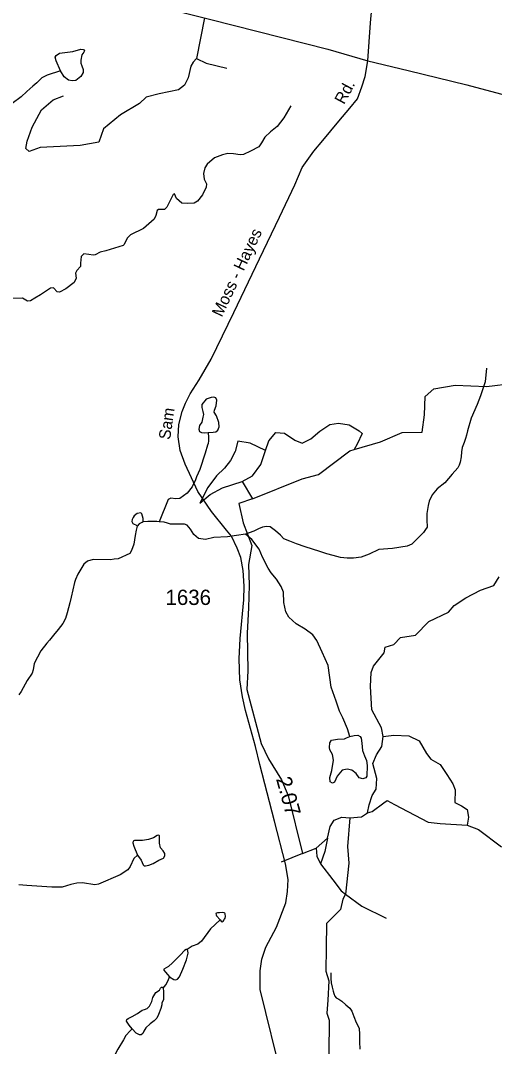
# Model space of a CAD drawing. Extents: x 2056842 to 2160602, y 826753 to 1016856.
# Drawn here: x 2101264 to 2105136, y 872458 to 880850 of the extents above; entities that cross this region are included whole.
import ezdxf

# ---------------------------------------------------------------- set-up
doc = ezdxf.new("R2010")
doc.units = 0
for name, color, linetype in [('Exist Hydrographic Misc Water Feature', 7, 'Continuous'), ('Exist Road Non-System Type 51', 7, 'Continuous'), ('Exist Road Secondary Mileage Hundredths English Label', 7, 'Continuous'), ('Exist Road Secondary Type 51 Attributed', 7, 'Continuous'), ('Exist Road Secondary Type 51 Label', 7, 'Continuous'), ('Exist Road Secondary Type 51 Number Label', 7, 'Continuous')]:
    doc.layers.add(name, color=color, linetype=linetype)

msp = doc.modelspace()

# ---------------------------------------------------------------- linework, layer by layer
at = {"layer": 'Exist Hydrographic Misc Water Feature'}
for points in [[(2101589.2, 880437.9), (2101555.1, 880520.6), (2101547.8, 880548.6), (2101555.1, 880564.4), (2101580.7, 880581.4), (2101690.1, 880597.3), (2101756.9, 880614.3), (2101778.8, 880611.8), (2101784.9, 880600.9), (2101780, 880591.2), (2101765.4, 880569.3), (2101756.9, 880524.3), (2101755.7, 880501.2), (2101765.4, 880478.1), (2101775.1, 880447.7), (2101775.1, 880423.3), (2101756.9, 880391.7), (2101714.4, 880360.1), (2101686.4, 880355.2), (2101654.8, 880361.3), (2101619.6, 880389.3), (2101589.2, 880437.9)], [(2101589.2, 880437.9), (2101482.2, 880401.5), (2101437.2, 880380.8), (2101397.5, 880340.9), (2101363.9, 880312.7), (2101315.7, 880268.5), (2101267.9, 880224.6), (2101196, 880172.2)], [(2103471.9, 880150.8), (2103413.6, 880054.7), (2103360.1, 879984.2), (2103306.6, 879939.2), (2103260.4, 879896.6), (2103233.7, 879850.4), (2103211.8, 879816.4), (2103143.7, 879779.9), (2103086.6, 879753.1), (2103058.6, 879751.9), (2103002.7, 879760.4), (2102956.8, 879761.9), (2102914.3, 879752.2), (2102848.6, 879725.4), (2102789.1, 879674.3), (2102769.6, 879645.1), (2102758.7, 879598.9), (2102763.5, 879552.7), (2102781.8, 879513.8), (2102780.6, 879485.8), (2102750.2, 879423.8), (2102710.1, 879370.9), (2102682.1, 879356.3), (2102628.6, 879352.7), (2102582.4, 879356.3), (2102538, 879392.8), (2102522.2, 879432.9), (2102511.2, 879426.8), (2102460.2, 879322.3), (2102439.5, 879305.2), (2102392.1, 879304), (2102379.9, 879295.5), (2102368.3, 879254), (2102356.1, 879224.8), (2102268.6, 879149.4), (2102162.9, 879097.1), (2102134.9, 879069.2), (2102109.4, 879018.1), (2102100.9, 879008.4), (2101959.9, 878964.6), (2101915.4, 878955.1), (2101872.9, 878932), (2101858.3, 878929.6), (2101820.6, 878936.9), (2101781.7, 878941.7), (2101758.6, 878919.8), (2101753.8, 878863.9), (2101753.8, 878838.4), (2101724.6, 878805.5), (2101713.6, 878782.4), (2101717.3, 878743.5), (2101701.5, 878705.8), (2101634.6, 878654.7), (2101582.4, 878629.2), (2101562.9, 878630.4), (2101533.8, 878663.2), (2101509.4, 878660.8), (2101428, 878604.9), (2101381.6, 878578.7), (2101345.1, 878556.8), (2101320.8, 878554.4), (2101279.5, 878579.9), (2101200.5, 878575.1)], [(2105070, 878007.1), (2105059, 877894.3), (2105022.6, 877780), (2104994.6, 877708.2), (2104946, 877597.5), (2104916, 877494.3), (2104908, 877458.3), (2104899.8, 877430.3), (2104888.1, 877398.4), (2104872.1, 877358.2), (2104866.6, 877322.1), (2104862.5, 877282.1), (2104854.7, 877238.3), (2104848.8, 877212), (2104836.9, 877191.9), (2104791.1, 877140), (2104731.3, 877067.9), (2104667.5, 877019.6), (2104627.7, 876969.6), (2104602.1, 876917.4), (2104593.9, 876883.4), (2104582, 876817.5), (2104582.6, 876785.3), (2104584.5, 876765.6), (2104585.3, 876706.8), (2104573.1, 876686.2), (2104554.9, 876660.9), (2104499, 876603.7), (2104461.3, 876566), (2104422.4, 876550.2), (2104303.3, 876532), (2104191.5, 876522.2), (2104113.2, 876485.9), (2104045.6, 876461.7), (2103985.3, 876451.4), (2103933.2, 876453.6), (2103877.4, 876457.2), (2103817.6, 876475.1), (2103765.5, 876486.7), (2103709.3, 876506.6), (2103589.3, 876544.2), (2103519, 876568.3), (2103463, 876591.8), (2103414.8, 876611.7), (2103386.7, 876639.8), (2103347, 876675.5), (2103304.5, 876707.5), (2103272.5, 876711.2), (2103240.3, 876707.1), (2103206.9, 876693.1), (2103171, 876672.9), (2103102.7, 876648.8)], [(2102797.3, 877480.3), (2102836.2, 877482.7), (2102859.3, 877486.4), (2102876.3, 877498.5), (2102886.1, 877527.7), (2102884.9, 877560.6), (2102864.2, 877615.3), (2102846, 877645.7), (2102848.4, 877661.5), (2102863, 877698), (2102866.6, 877744.2), (2102858.1, 877762.4), (2102843.5, 877768.5), (2102821.7, 877766.1), (2102780.3, 877751.5), (2102746.3, 877710.2), (2102743.9, 877685.8), (2102752.4, 877650.6), (2102758.4, 877626.2), (2102753.6, 877605.6), (2102743.9, 877565.4), (2102726.8, 877536.2), (2102720.8, 877508.3), (2102726.8, 877487.6), (2102741.4, 877480.3), (2102768.2, 877477.9), (2102797.3, 877480.3)], [(2102797.3, 877480.3), (2102799.8, 877439), (2102800.5, 877411.6), (2102796.1, 877391.5), (2102790.9, 877375.7), (2102771.8, 877310.3), (2102728.1, 877177.7), (2102702.5, 877116.9), (2102694, 877092.6), (2102667.3, 877035.4), (2102624.8, 876984.2), (2102565.9, 876939.1), (2102531.9, 876938), (2102491.8, 876944.1), (2102471.1, 876933.2), (2102396.5, 876750.5)], [(2102264.7, 876748.2), (2102264.7, 876760), (2102264.7, 876776.2), (2102254.9, 876815.8), (2102246.5, 876822), (2102216.5, 876818), (2102192.7, 876798.1), (2102184.5, 876783.9), (2102176.7, 876767.6), (2102172.8, 876752), (2102180.6, 876735.8), (2102192.9, 876729.9), (2102205, 876726), (2102216.9, 876714)], [(2102216.9, 876714), (2102207.1, 876681.8), (2102199.3, 876638.1), (2102189.4, 876566.1), (2102169.6, 876515.9), (2102157.5, 876491.7), (2102061.7, 876447.5), (2102029.5, 876443.4), (2101997.5, 876439.4), (2101856.1, 876441.5), (2101811.1, 876426.9), (2101782, 876402.6), (2101732.1, 876321.1), (2101712.3, 876278.4), (2101704.5, 876254.5), (2101678.5, 876134.2), (2101665.1, 876086.4), (2101644.8, 876006.2), (2101631.3, 875958.4), (2101610.3, 875918.2), (2101571.6, 875870), (2101531.8, 875822), (2101500.1, 875781.9), (2101477.7, 875757.7), (2101430.1, 875693.9), (2101374.4, 875591.6), (2101367.3, 875538.1), (2101358.7, 875511.4), (2101317.4, 875453), (2101269.2, 875363.1), (2101249.3, 875334.9)], [(2102264.7, 876748.2), (2102256.9, 876744.1), (2102248.9, 876740.1), (2102233.1, 876733.9), (2102216.9, 876714)], [(2102396.5, 876750.5), (2102376.9, 876752.3), (2102304.5, 876752.3), (2102264.7, 876748.2)], [(2103102.7, 876648.8), (2102954.9, 876626.6), (2102843.4, 876622), (2102775.3, 876606), (2102717, 876613.5), (2102678.9, 876645.2), (2102651, 876689.2), (2102624.8, 876721.2), (2102604.5, 876729.2), (2102572.5, 876731.1), (2102524.9, 876731), (2102488.8, 876730.8), (2102464.6, 876738.6), (2102436.5, 876746.5), (2102396.5, 876750.5)], [(2103953.7, 874992.7), (2103934.3, 875055.9), (2103897.3, 875145.5), (2103869.2, 875201.4), (2103841.3, 875283.5), (2103800.6, 875396.7), (2103778, 875575.1), (2103727.5, 875682.9), (2103683.7, 875778.9), (2103651.3, 875826.4), (2103590.5, 875871.6), (2103515.2, 875914.2), (2103455.6, 875968.9), (2103431.3, 876012.4), (2103415.5, 876090.3), (2103412.4, 876173.8), (2103391.9, 876221.5), (2103356.2, 876279.7), (2103312.1, 876331.4), (2103286.1, 876371.5), (2103241.2, 876459.5), (2103213.3, 876526.9), (2103154.8, 876604.8), (2103102.7, 876648.8)], [(2103953.7, 874992.7), (2103989, 875002.4), (2104019.3, 875003.6), (2104038.8, 874993.9), (2104047.3, 874979.3), (2104050.9, 874938), (2104057, 874879.6), (2104072.8, 874835.8), (2104089.8, 874798.1), (2104094.7, 874756.8), (2104092.3, 874669.2), (2104086.2, 874655.8), (2104060.7, 874648.5), (2104031.5, 874655.8), (2104007.2, 874689.9), (2103970.7, 874717.8), (2103931.8, 874726.4), (2103890.5, 874717.8), (2103851.6, 874668), (2103829.7, 874620.6), (2103811.5, 874612), (2103793.3, 874623), (2103790.8, 874659.5), (2103807.9, 874716.6), (2103821.2, 874800.5), (2103813.9, 874845.5), (2103792.1, 874885.7), (2103788.4, 874902.7), (2103789.6, 874942.8), (2103805.4, 874963.5), (2103852.8, 874973.2), (2103910, 874974.4), (2103927, 874981.7), (2103953.7, 874992.7)], [(2102220, 874024), (2102248, 873982.3), (2102265, 873943.4), (2102274.7, 873934.9), (2102284.4, 873934.9), (2102311.2, 873942.2), (2102347.6, 873954.4), (2102393.8, 873983.5), (2102432.7, 873999.3), (2102442.4, 874016.4), (2102442.4, 874035.8), (2102427.9, 874058.9), (2102408.4, 874083.3), (2102399.9, 874122.2), (2102398.7, 874180.6), (2102393.8, 874186.6), (2102380.4, 874184.2), (2102348.8, 874166), (2102310, 874150.2), (2102260.1, 874142.9), (2102195.7, 874142.9), (2102183.5, 874136.8), (2102181.1, 874124.6), (2102188.4, 874096.6), (2102220, 874024)], [(2102220, 874024), (2102189.6, 873994.8), (2102160.5, 873931.6), (2102139.8, 873903.6), (2102078, 873862.3), (2101901.8, 873785.7), (2101871.4, 873779.6), (2101770.5, 873797.8), (2101724.4, 873795.4), (2101674.5, 873782), (2101604, 873761.4), (2101518.9, 873762.6), (2101314.3, 873775.4), (2101250.3, 873779.5)], [(2102894.8, 873494.5), (2102902.6, 873482.4), (2102911, 873478.7), (2102918.8, 873482.4), (2102926.8, 873494.6), (2102930.9, 873498.8), (2102934.8, 873506.8), (2102938.7, 873522.8), (2102936.5, 873542.6), (2102932.4, 873548.5), (2102928.5, 873550.7), (2102912.7, 873554.8), (2102888.9, 873552.6), (2102872.9, 873550.7), (2102864.7, 873548.2), (2102860.6, 873546.4), (2102860.8, 873534.2), (2102864.5, 873526.4), (2102894.8, 873494.5)], [(2102894.8, 873494.5), (2102817.1, 873420.3), (2102741.9, 873319.3), (2102711.5, 873295), (2102666.6, 873277.9), (2102625.2, 873251.2)], [(2102625.2, 873251.2), (2102618, 873252.4), (2102604.6, 873243.9), (2102569.3, 873208.6), (2102538.9, 873175.8), (2102506.1, 873141.7), (2102473.3, 873113.8), (2102435.6, 873090.7), (2102435.6, 873083.4), (2102449, 873066.3), (2102481.8, 873026.8)], [(2102481.8, 873026.8), (2102515.9, 873005.5), (2102532.9, 873004.3), (2102545, 873008), (2102563.3, 873028.6), (2102590, 873091.9), (2102619.2, 873167.3), (2102632.5, 873222), (2102631.3, 873241.5), (2102625.2, 873251.2)], [(2102428.3, 872934.4), (2102450.2, 872963.6), (2102470.9, 872997.6), (2102481.8, 873026.8)], [(2103798.1, 873059.5), (2103798.1, 873015.2), (2103802.4, 872977.7), (2103810.2, 872943.6), (2103818.6, 872911.5), (2103822.9, 872891.3), (2103830.7, 872869.5), (2103842.8, 872857.5), (2103864.5, 872845.7), (2103888.3, 872827.9), (2103921.1, 872799.8), (2103952.9, 872771.8), (2103971.1, 872748), (2103987.1, 872704.1), (2104005.4, 872655.9), (2104029.4, 872608.1), (2104033.9, 872556.3), (2104034.1, 872496.2), (2104035.9, 872436.2)], [(2102174.8, 872602.1), (2102150, 872631.6), (2102129.3, 872665.6), (2102131.8, 872677.8), (2102142.7, 872686.3), (2102175.5, 872704.5), (2102218.1, 872728.9), (2102257, 872755.6), (2102277.6, 872760.5), (2102299.5, 872770.2), (2102316.5, 872787.2), (2102336, 872827.4), (2102343.3, 872860.2), (2102370, 872900.3), (2102399.2, 872919.8), (2102407.7, 872935.6), (2102415, 872942.9), (2102421.1, 872942.9), (2102428.3, 872934.4)], [(2102428.3, 872934.4), (2102430.8, 872908.8), (2102432, 872865.1), (2102432, 872839.5), (2102418.6, 872816.4), (2102417.4, 872798.2), (2102408.9, 872770.2), (2102390.7, 872720.3), (2102376.1, 872691.2), (2102354.2, 872669.3), (2102323.8, 872644.9), (2102287.4, 872612.1), (2102271.6, 872584.1), (2102263, 872564.7), (2102249.7, 872553.7), (2102236.3, 872554.9), (2102207.1, 872568.3), (2102174.8, 872602.1)], [(2102174.8, 872602.1), (2102159, 872586.3), (2102125, 872547.4), (2102104.3, 872513.4), (2102059.3, 872435.5), (2102020.4, 872362.6), (2101962.1, 872294.7), (2101918.3, 872243.6), (2101900.1, 872225.4), (2101853.4, 872181.2)]]:
    msp.add_lwpolyline(points, dxfattribs=at)
at = {"layer": 'Exist Road Non-System Type 51'}
for p, q in [((2102766.6, 880870.3), (2102701.6, 880538.3)), ((2103074.5, 877079), (2103160, 876938.2)), ((2103678.8, 874080.3), (2103771.9, 874162)), ((2103568.6, 874036.5), (2103393.8, 873966.2)), ((2103568.6, 874036.5), (2103678.8, 874080.3))]:
    msp.add_line(p, q, dxfattribs=at)
for points in [[(2102701.6, 880538.3), (2102675, 880509.8), (2102654.1, 880475.5), (2102633.2, 880380.5), (2102602.8, 880319.6), (2102555.3, 880283.5), (2102395.7, 880249.3), (2102290.2, 880221.7), (2102237, 880172.3), (2102081.2, 880077.2), (2101942.5, 879963.1), (2101902.6, 879854.7), (2101749.6, 879827.1), (2101424.7, 879810), (2101335.3, 879779.6), (2101306.8, 879802.4), (2101318.2, 879863.3), (2101358.1, 879977.3), (2101434.2, 880120), (2101529.2, 880201.7), (2101614.7, 880234)], [(2102701.6, 880538.3), (2102779.5, 880502.2), (2102950.5, 880460.3)], [(2103989.5, 877340.4), (2104204.2, 877405.1), (2104382.8, 877481.1), (2104546.3, 877483), (2104563.4, 877625.6), (2104571, 877774), (2104639.4, 877838.6), (2104816.1, 877867.1), (2105070.7, 877857.6), (2105296.8, 877884.2), (2105507.8, 877966), (2105738.7, 878024), (2105974.3, 878046.8), (2106160.5, 878067.7), (2106325.8, 878063.9), (2106325.8, 878044.9)], [(2103266.5, 877333.8), (2103292.1, 877410.8), (2103349.1, 877481.1), (2103421.3, 877473.5), (2103504.9, 877416.5), (2103565.7, 877391.8), (2103636, 877427.9), (2103710.2, 877490.6), (2103790, 877545.8), (2103862.2, 877557.2), (2103947.7, 877542), (2104031.3, 877492.5), (2104056, 877471.6), (2104014.2, 877384.2), (2103989.5, 877340.4)], [(2103266.5, 877333.8), (2103140.1, 877391.8), (2103040.3, 877409.8), (2103017.5, 877324.3), (2102979.5, 877250.1), (2102930.1, 877189.2), (2102865.5, 877126.5), (2102795.2, 877029.5), (2102728.7, 876902.1), (2102812.3, 876972.5), (2102914.9, 877027.6), (2103074.5, 877079)], [(2103074.5, 877079), (2103158.1, 877126.5), (2103226.5, 877217.8), (2103266.5, 877333.8)], [(2103160, 876938.2), (2103564.8, 877101.8), (2103697.8, 877137.9), (2103953.4, 877329), (2103989.5, 877340.4)], [(2103160, 876938.2), (2103047.9, 876898.3), (2103082.1, 876740.5), (2103154.3, 876556), (2103125.8, 876400.1), (2103132.5, 876231.8), (2103124.9, 876047.4), (2103115.4, 875840.1), (2103121.1, 875530.2), (2103112.5, 875377.1), (2103228.4, 874936), (2103290.2, 874811.4), (2103396.6, 874640.3), (2103451.7, 874511), (2103568.6, 874036.5)], [(2104226.1, 874994.9), (2104212.8, 875063.4), (2104134.9, 875211.7), (2104123.5, 875403.7), (2104129.2, 875515.9), (2104146.3, 875569.2), (2104233.7, 875679.4), (2104242.2, 875724.1), (2104314.4, 875746.9), (2104369.5, 875802.1), (2104491.2, 875823), (2104599.5, 875935.2), (2104759.1, 876009.4), (2104807.1, 876065), (2104903, 876127.7), (2105020.8, 876191.4), (2105129.6, 876229.9), (2105174.3, 876298.4)], [(2104097.8, 874368.3), (2104111.1, 874434.9), (2104137.7, 874511), (2104170, 874562.3), (2104175.7, 874649.8), (2104141.5, 874773.4), (2104171.9, 874843.7), (2104216.6, 874913.1), (2104226.1, 874994.9)], [(2104226.1, 874994.9), (2104314.4, 875005.4), (2104436, 874999.6), (2104521.6, 874957.8), (2104580.5, 874855.1), (2104614.7, 874807.6), (2104692.6, 874765.8), (2104747.7, 874682.1), (2104797.1, 874607.9), (2104816.1, 874556.6), (2104812.3, 874453.9), (2104867.4, 874425.4), (2104913, 874396.9), (2104922.5, 874334.1), (2104913, 874269.5)], [(2104097.8, 874368.3), (2104137.7, 874381.7), (2104230.8, 874452), (2104259.3, 874469.1), (2104318.2, 874436.8), (2104593.8, 874292.3), (2104692.6, 874280.9), (2104913, 874269.5)], [(2103954.3, 874329.4), (2104048.4, 874336), (2104097.8, 874368.3)], [(2103771.9, 874162), (2103794.7, 874259), (2103827, 874310.4), (2103887.8, 874333.2), (2103954.3, 874329.4)], [(2103954.3, 874329.4), (2103935.3, 874093.6), (2103944.8, 873958.6), (2103918.2, 873703.8)], [(2104913, 874269.5), (2105005.2, 874232.4), (2105193.3, 874091.7)], [(2103771.9, 874162), (2103751, 874053.6), (2103714.9, 873952.9)], [(2103678.8, 874080.3), (2103684.5, 874015.6), (2103714.9, 873952.9)], [(2103714.9, 873952.9), (2103815.6, 873821.7), (2103884, 873730.4), (2103918.2, 873703.8)], [(2103918.2, 873703.8), (2103896.4, 873662.9), (2103877.4, 873579.2), (2103824.2, 873524.1), (2103763.4, 873465.1), (2103759.6, 873265.5), (2103758.6, 873074.4), (2103783.3, 872996.4), (2103773.8, 872838.6), (2103766.2, 872732.1), (2103785.2, 872673.1), (2103781.4, 872399.3)], [(2103918.2, 873703.8), (2104053.1, 873604.9), (2104250.8, 873507.9)]]:
    msp.add_lwpolyline(points, dxfattribs=at)
at = {"layer": 'Exist Road Secondary Type 51 Attributed'}
for points in [[(2104100.7, 880519.5), (2104122.1, 880830.9), (2104162, 881245.4)], [(2096859.3, 881046.2), (2097184.2, 881105.2), (2097438.8, 881135.6), (2097681.1, 881136.6), (2098066.8, 881089), (2098433.5, 881064.3), (2098936.1, 881038.6), (2099325.7, 881029.1), (2099641.1, 881027.2), (2100103.8, 881052.9), (2100584.5, 881096.6), (2101052.9, 881143.2), (2101347.4, 881166), (2101579.2, 881156.5), (2101723.6, 881128), (2102207.2, 881011.1), (2102819.1, 880857), (2103773.9, 880616.5), (2104100.7, 880519.5)], [(2103358, 872371.8), (2103267.3, 872737.3), (2103221.7, 872923.7), (2103220.3, 873077.2), (2103234.5, 873173.2), (2103268.7, 873270.2), (2103354.7, 873434.2), (2103432.6, 873633.8), (2103445, 873725.1), (2103449.2, 873825.4), (2103428.3, 873951.9), (2103338.6, 874302.2), (2103218.4, 874764.7), (2103183.2, 874913), (2103102.9, 875206.3), (2103078.2, 875317.6), (2103054.5, 875457.3), (2103050.2, 875629.9), (2103058.8, 875795.3), (2103086.8, 876110.5), (2103091.5, 876223.6), (2103083, 876350.1), (2103062.6, 876458), (2103033.1, 876533.1), (2102986.6, 876631), (2102945.7, 876682.4), (2102824.6, 876834.9), (2102713.4, 876998.5), (2102607.5, 877220.5), (2102567.6, 877332.7), (2102550.5, 877443.9), (2102555.7, 877545.1), (2102583.2, 877650.7), (2102610.8, 877720.1), (2102648.8, 877797.1), (2102724.3, 877909.7), (2102822, 878080.2), (2103006.7, 878460.9), (2103217.2, 878900.6), (2103378.2, 879242.4), (2103504.6, 879506.7), (2103565.9, 879647.9), (2103660.9, 879780.1), (2103734, 879867.5), (2103865.6, 880026.8), (2103954.9, 880132.3), (2104015.7, 880209.3), (2104051.8, 880306.3), (2104079.9, 880392.3), (2104100.7, 880519.5)], [(2104100.7, 880519.5), (2104430.4, 880441.8), (2104909.3, 880323.9), (2105869.8, 880068.1), (2106333.5, 879952.1), (2107326.3, 879707.8), (2107674, 879614.6), (2107979.5, 879496.3), (2108213.2, 879379.3), (2108615.6, 879186.8), (2108856.9, 879065.1), (2109589.9, 878697.7), (2110032.1, 878502.3), (2110383.7, 878379.6), (2110888.6, 878198.5), (2111059.2, 878126.7)]]:
    msp.add_lwpolyline(points, dxfattribs=at)

# ---------------------------------------------------------------- texts
at = {"layer": 'Exist Road Secondary Mileage Hundredths English Label'}
msp.add_text('2.07', height=125, rotation=285.24581, dxfattribs=at).set_placement((2103350.4, 874647.2))
at = {"layer": 'Exist Road Secondary Type 51 Label'}
for s, rotation, p in [('Rd.', 61.8001, (2103907.3, 880157.5)), ('Moss - Hayes', 64.69262, (2102907.8, 878418.8)), ('Sam', 81.66265, (2102485.2, 877416.8))]:
    msp.add_text(s, height=95, rotation=rotation, dxfattribs=at).set_placement(p)
at = {"layer": 'Exist Road Secondary Type 51 Number Label'}
msp.add_text('1636', height=125, dxfattribs=at).set_placement((2102448.1, 876069.5))

doc.saveas('drawing.dxf')
